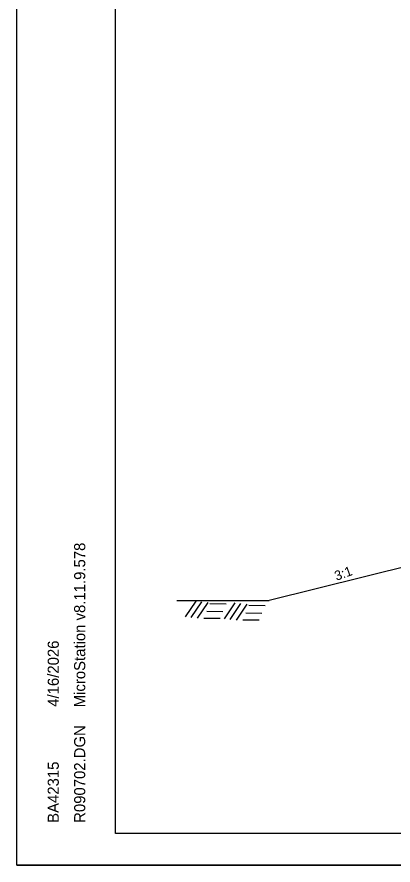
# Model space of a CAD drawing. Extents: x 1371763 to 1372860, y 385599 to 385872.
# Drawn here: x 1372293 to 1372316.7, y 385598.6 to 385651.9 of the extents above; entities that cross this region are included whole.
import ezdxf

# ---------------------------------------------------------------- set-up
doc = ezdxf.new("R2010")
doc.units = 0
for name, color, linetype in [('R_Border', 7, 'Continuous'), ('R_Draft', 7, 'Continuous'), ('R_Fin Surface', 7, 'Continuous'), ('R_No Plot', 7, 'Continuous')]:
    doc.layers.add(name, color=color, linetype=linetype)

msp = doc.modelspace()

# ---------------------------------------------------------------- linework, layer by layer
at = {"layer": 'R_Border'}
for p, q in [((1372299.208, 385600.577), (1372299.208, 385703.307)), ((1372299.208, 385600.577), (1372299.208, 385600.577)), ((1372457.298, 385600.577), (1372299.208, 385600.577))]:
    msp.add_line(p, q, dxfattribs=at)
at = {"layer": 'R_Draft'}
for p, q in [((1372318.579, 385617.642), (1372308.878, 385615.217)), ((1372303.613, 385614.186), (1372304.289, 385615.187)), ((1372303.972, 385614.144), (1372304.648, 385615.145)), ((1372304.373, 385614.102), (1372305.049, 385615.104)), ((1372305.149, 385615.029), (1372306.166, 385615.02)), ((1372306.066, 385614.077), (1372306.742, 385615.079)), ((1372306.425, 385614.035), (1372307.101, 385615.037)), ((1372306.826, 385613.994), (1372307.501, 385614.995)), ((1372307.601, 385614.92), (1372308.619, 385614.912)), ((1372304.773, 385614.119), (1372305.791, 385614.111)), ((1372304.948, 385614.545), (1372305.966, 385614.536)), ((1372307.401, 385614.436), (1372308.419, 385614.428)), ((1372307.226, 385614.01), (1372308.244, 385614.002))]:
    msp.add_line(p, q, dxfattribs=at)
at = {"layer": 'R_Fin Surface'}
msp.add_line((1372303.06, 385615.217), (1372308.878, 385615.217), dxfattribs=at)
at = {"layer": 'R_No Plot'}
msp.add_line((1372293.007, 385598.587), (1372459.674, 385598.587), dxfattribs=at)
for points in [[(1372293.004, 385705.254), (1372459.674, 385705.254), (1372459.674, 385598.585), (1372293.004, 385598.585)], [(1372416.168, 385703.307), (1372425.978, 385703.307), (1372425.978, 385698.367), (1372434.034, 385698.367), (1372445.634, 385698.367), (1372445.634, 385682.032), (1372457.238, 385682.032), (1372457.298, 385600.577), (1372299.208, 385600.577), (1372299.208, 385703.307)]]:
    msp.add_lwpolyline(points, close=True, dxfattribs=at)

# ---------------------------------------------------------------- texts
at = {"layer": 'R_Border'}
for s, p in [('MicroStation v8.11.9.578', (1372297.303, 385608.505)), ('4/16/2026', (1372295.64, 385608.54)), ('R090702.DGN', (1372297.303, 385601.239)), ('BA42315', (1372295.64, 385601.239))]:
    msp.add_text(s, height=0.7, rotation=90, dxfattribs=at).set_placement(p)
at = {"layer": 'R_Draft'}
msp.add_text('3:1', height=0.6, rotation=19.9978, dxfattribs=at).set_placement((1372313.119, 385616.458))

doc.saveas('drawing.dxf')
